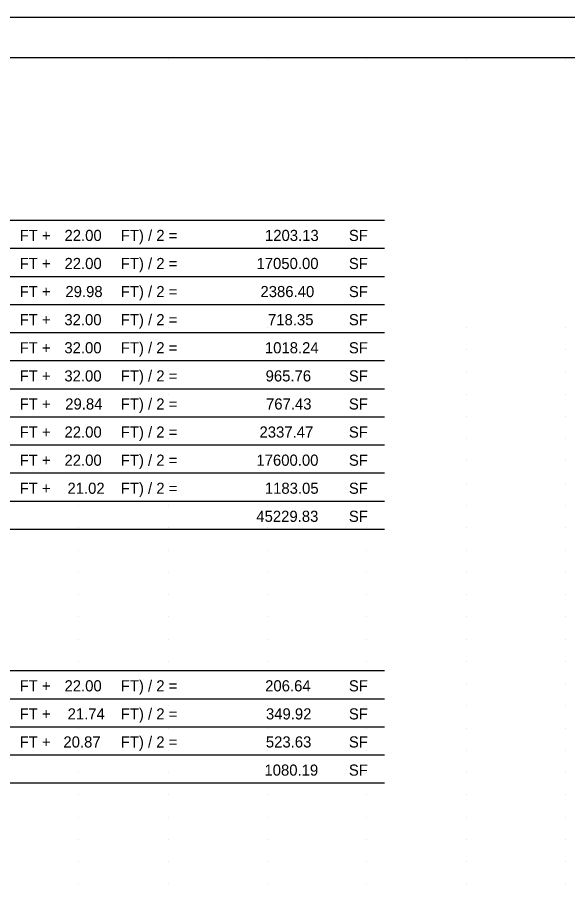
# Model space of a CAD drawing. Extents: x 2073163.5 to 2073197.5, y 634076.4 to 634098.4.
# Drawn here: x 2073173.43 to 2073180.34, y 634087.36 to 634098.43 of the extents above; entities that cross this region are included whole.
import ezdxf

# ---------------------------------------------------------------- set-up
doc = ezdxf.new("R2010")
doc.units = 0
for name, color, linetype in [('SC_Scratch1', 7, 'Continuous'), ('SH_Border', 7, 'Continuous'), ('SH_Cut_Line', 7, 'Continuous'), ('SH_Data', 7, 'Continuous'), ('SH_Text', 7, 'Continuous')]:
    doc.layers.add(name, color=color, linetype=linetype)

msp = doc.modelspace()

# ---------------------------------------------------------------- linework, layer by layer
at = {"layer": 'SC_Scratch1'}
for p, q in [((2073165.829, 634095.887), (2073178.043, 634095.887)), ((2073165.829, 634095.533), (2073178.043, 634095.533)), ((2073165.829, 634095.18), (2073178.043, 634095.18)), ((2073165.829, 634094.827), (2073178.043, 634094.827)), ((2073165.829, 634094.473), (2073178.043, 634094.473)), ((2073165.829, 634094.12), (2073178.043, 634094.12)), ((2073165.829, 634093.767), (2073178.043, 634093.767)), ((2073165.829, 634093.413), (2073178.043, 634093.413)), ((2073165.829, 634093.06), (2073178.043, 634093.06)), ((2073165.829, 634092.707), (2073178.043, 634092.707)), ((2073165.829, 634092.353), (2073178.043, 634092.353)), ((2073165.829, 634092), (2073178.043, 634092)), ((2073165.829, 634090.222), (2073178.043, 634090.222)), ((2073165.829, 634089.868), (2073178.043, 634089.868)), ((2073165.829, 634089.515), (2073178.043, 634089.515)), ((2073165.829, 634089.162), (2073178.043, 634089.162)), ((2073165.829, 634088.808), (2073178.043, 634088.808))]:
    msp.add_line(p, q, dxfattribs=at)
at = {"layer": 'SH_Border'}
msp.add_lwpolyline([(2073165.007, 634097.934), (2073197.007, 634097.934), (2073197.007, 634076.934), (2073165.007, 634076.934)], close=True, dxfattribs=at)
at = {"layer": 'SH_Cut_Line'}
msp.add_lwpolyline([(2073163.507, 634076.434), (2073197.507, 634076.434), (2073197.507, 634098.434), (2073163.507, 634098.434)], close=True, dxfattribs=at)
at = {"layer": 'SH_Data'}
for p, q in [((2073175.321, 634097.91), (2073175.321, 634097.91)), ((2073176.571, 634097.91), (2073176.571, 634097.91)), ((2073177.821, 634097.91), (2073177.821, 634097.91)), ((2073179.071, 634097.91), (2073179.071, 634097.91)), ((2073180.321, 634097.91), (2073180.321, 634097.91)), ((2073175.321, 634094.538), (2073175.321, 634094.538)), ((2073176.571, 634094.538), (2073176.571, 634094.538)), ((2073177.821, 634094.538), (2073177.821, 634094.538)), ((2073179.071, 634094.538), (2073179.071, 634094.538)), ((2073180.321, 634094.538), (2073180.321, 634094.538)), ((2073174.196, 634094.258), (2073174.196, 634094.258)), ((2073175.321, 634094.258), (2073175.321, 634094.258)), ((2073176.571, 634094.258), (2073176.571, 634094.258)), ((2073177.821, 634094.258), (2073177.821, 634094.258)), ((2073179.071, 634094.258), (2073179.071, 634094.258)), ((2073180.321, 634094.258), (2073180.321, 634094.258)), ((2073174.196, 634093.978), (2073174.196, 634093.978)), ((2073175.321, 634093.978), (2073175.321, 634093.978)), ((2073176.571, 634093.978), (2073176.571, 634093.978)), ((2073177.821, 634093.978), (2073177.821, 634093.978)), ((2073179.071, 634093.978), (2073179.071, 634093.978)), ((2073180.321, 634093.978), (2073180.321, 634093.978)), ((2073174.196, 634093.698), (2073174.196, 634093.698)), ((2073175.321, 634093.698), (2073175.321, 634093.698)), ((2073176.571, 634093.698), (2073176.571, 634093.698)), ((2073177.821, 634093.698), (2073177.821, 634093.698)), ((2073179.071, 634093.698), (2073179.071, 634093.698)), ((2073180.321, 634093.698), (2073180.321, 634093.698)), ((2073174.196, 634093.418), (2073174.196, 634093.418)), ((2073175.321, 634093.418), (2073175.321, 634093.418)), ((2073176.571, 634093.418), (2073176.571, 634093.418)), ((2073177.821, 634093.418), (2073177.821, 634093.418)), ((2073179.071, 634093.418), (2073179.071, 634093.418)), ((2073180.321, 634093.418), (2073180.321, 634093.418)), ((2073174.196, 634093.138), (2073174.196, 634093.138)), ((2073175.321, 634093.138), (2073175.321, 634093.138)), ((2073176.571, 634093.138), (2073176.571, 634093.138)), ((2073177.821, 634093.138), (2073177.821, 634093.138)), ((2073179.071, 634093.138), (2073179.071, 634093.138)), ((2073180.321, 634093.138), (2073180.321, 634093.138)), ((2073174.196, 634092.858), (2073174.196, 634092.858)), ((2073175.321, 634092.858), (2073175.321, 634092.858)), ((2073176.571, 634092.858), (2073176.571, 634092.858)), ((2073177.821, 634092.858), (2073177.821, 634092.858)), ((2073179.071, 634092.858), (2073179.071, 634092.858)), ((2073180.321, 634092.858), (2073180.321, 634092.858)), ((2073174.196, 634092.578), (2073174.196, 634092.578)), ((2073175.321, 634092.578), (2073175.321, 634092.578)), ((2073176.571, 634092.578), (2073176.571, 634092.578)), ((2073177.821, 634092.578), (2073177.821, 634092.578)), ((2073179.071, 634092.578), (2073179.071, 634092.578)), ((2073180.321, 634092.578), (2073180.321, 634092.578)), ((2073174.196, 634092.298), (2073174.196, 634092.298)), ((2073175.321, 634092.298), (2073175.321, 634092.298)), ((2073176.571, 634092.298), (2073176.571, 634092.298)), ((2073177.821, 634092.298), (2073177.821, 634092.298)), ((2073179.071, 634092.298), (2073179.071, 634092.298)), ((2073180.321, 634092.298), (2073180.321, 634092.298)), ((2073174.196, 634092.018), (2073174.196, 634092.018)), ((2073175.321, 634092.018), (2073175.321, 634092.018)), ((2073176.571, 634092.018), (2073176.571, 634092.018)), ((2073177.821, 634092.018), (2073177.821, 634092.018)), ((2073179.071, 634092.018), (2073179.071, 634092.018)), ((2073180.321, 634092.018), (2073180.321, 634092.018)), ((2073174.196, 634091.738), (2073174.196, 634091.738)), ((2073175.321, 634091.738), (2073175.321, 634091.738)), ((2073176.571, 634091.738), (2073176.571, 634091.738)), ((2073177.821, 634091.738), (2073177.821, 634091.738)), ((2073179.071, 634091.738), (2073179.071, 634091.738)), ((2073180.321, 634091.738), (2073180.321, 634091.738)), ((2073174.196, 634091.458), (2073174.196, 634091.458)), ((2073175.321, 634091.458), (2073175.321, 634091.458)), ((2073176.571, 634091.458), (2073176.571, 634091.458)), ((2073177.821, 634091.458), (2073177.821, 634091.458)), ((2073179.071, 634091.458), (2073179.071, 634091.458)), ((2073180.321, 634091.458), (2073180.321, 634091.458)), ((2073174.196, 634091.178), (2073174.196, 634091.178)), ((2073175.321, 634091.178), (2073175.321, 634091.178)), ((2073176.571, 634091.178), (2073176.571, 634091.178)), ((2073177.821, 634091.178), (2073177.821, 634091.178)), ((2073179.071, 634091.178), (2073179.071, 634091.178)), ((2073180.321, 634091.178), (2073180.321, 634091.178)), ((2073174.196, 634090.898), (2073174.196, 634090.898)), ((2073175.321, 634090.898), (2073175.321, 634090.898)), ((2073176.571, 634090.898), (2073176.571, 634090.898)), ((2073177.821, 634090.898), (2073177.821, 634090.898)), ((2073179.071, 634090.898), (2073179.071, 634090.898)), ((2073180.321, 634090.898), (2073180.321, 634090.898)), ((2073174.196, 634090.618), (2073174.196, 634090.618)), ((2073175.321, 634090.618), (2073175.321, 634090.618)), ((2073176.571, 634090.618), (2073176.571, 634090.618)), ((2073177.821, 634090.618), (2073177.821, 634090.618)), ((2073179.071, 634090.618), (2073179.071, 634090.618)), ((2073180.321, 634090.618), (2073180.321, 634090.618)), ((2073174.196, 634090.338), (2073174.196, 634090.338)), ((2073175.321, 634090.338), (2073175.321, 634090.338)), ((2073176.571, 634090.338), (2073176.571, 634090.338)), ((2073177.821, 634090.338), (2073177.821, 634090.338)), ((2073179.071, 634090.338), (2073179.071, 634090.338)), ((2073180.321, 634090.338), (2073180.321, 634090.338)), ((2073174.196, 634090.058), (2073174.196, 634090.058)), ((2073175.321, 634090.058), (2073175.321, 634090.058)), ((2073176.571, 634090.058), (2073176.571, 634090.058)), ((2073177.821, 634090.058), (2073177.821, 634090.058)), ((2073179.071, 634090.058), (2073179.071, 634090.058)), ((2073180.321, 634090.058), (2073180.321, 634090.058)), ((2073174.196, 634089.778), (2073174.196, 634089.778)), ((2073175.321, 634089.778), (2073175.321, 634089.778)), ((2073176.571, 634089.778), (2073176.571, 634089.778)), ((2073177.821, 634089.778), (2073177.821, 634089.778)), ((2073179.071, 634089.778), (2073179.071, 634089.778)), ((2073180.321, 634089.778), (2073180.321, 634089.778)), ((2073174.196, 634089.498), (2073174.196, 634089.498)), ((2073175.321, 634089.498), (2073175.321, 634089.498)), ((2073176.571, 634089.498), (2073176.571, 634089.498)), ((2073177.821, 634089.498), (2073177.821, 634089.498)), ((2073179.071, 634089.498), (2073179.071, 634089.498)), ((2073180.321, 634089.498), (2073180.321, 634089.498)), ((2073174.196, 634089.218), (2073174.196, 634089.218)), ((2073175.321, 634089.218), (2073175.321, 634089.218)), ((2073176.571, 634089.218), (2073176.571, 634089.218)), ((2073177.821, 634089.218), (2073177.821, 634089.218)), ((2073179.071, 634089.218), (2073179.071, 634089.218)), ((2073180.321, 634089.218), (2073180.321, 634089.218)), ((2073174.196, 634088.938), (2073174.196, 634088.938)), ((2073175.321, 634088.938), (2073175.321, 634088.938)), ((2073176.571, 634088.938), (2073176.571, 634088.938)), ((2073177.821, 634088.938), (2073177.821, 634088.938)), ((2073179.071, 634088.938), (2073179.071, 634088.938)), ((2073180.321, 634088.938), (2073180.321, 634088.938)), ((2073174.196, 634088.658), (2073174.196, 634088.658)), ((2073175.321, 634088.658), (2073175.321, 634088.658)), ((2073176.571, 634088.658), (2073176.571, 634088.658)), ((2073177.821, 634088.658), (2073177.821, 634088.658)), ((2073179.071, 634088.658), (2073179.071, 634088.658)), ((2073180.321, 634088.658), (2073180.321, 634088.658)), ((2073174.196, 634088.378), (2073174.196, 634088.378)), ((2073175.321, 634088.378), (2073175.321, 634088.378)), ((2073176.571, 634088.378), (2073176.571, 634088.378)), ((2073177.821, 634088.378), (2073177.821, 634088.378)), ((2073179.071, 634088.378), (2073179.071, 634088.378)), ((2073180.321, 634088.378), (2073180.321, 634088.378)), ((2073174.196, 634088.098), (2073174.196, 634088.098)), ((2073175.321, 634088.098), (2073175.321, 634088.098)), ((2073176.571, 634088.098), (2073176.571, 634088.098)), ((2073177.821, 634088.098), (2073177.821, 634088.098)), ((2073179.071, 634088.098), (2073179.071, 634088.098)), ((2073180.321, 634088.098), (2073180.321, 634088.098)), ((2073174.196, 634087.818), (2073174.196, 634087.818)), ((2073175.321, 634087.818), (2073175.321, 634087.818)), ((2073176.571, 634087.818), (2073176.571, 634087.818)), ((2073177.821, 634087.818), (2073177.821, 634087.818)), ((2073179.071, 634087.818), (2073179.071, 634087.818)), ((2073180.321, 634087.818), (2073180.321, 634087.818)), ((2073174.196, 634087.538), (2073174.196, 634087.538)), ((2073175.321, 634087.538), (2073175.321, 634087.538)), ((2073176.571, 634087.538), (2073176.571, 634087.538)), ((2073177.821, 634087.538), (2073177.821, 634087.538)), ((2073179.071, 634087.538), (2073179.071, 634087.538)), ((2073180.321, 634087.538), (2073180.321, 634087.538))]:
    msp.add_line(p, q, dxfattribs=at)

# ---------------------------------------------------------------- texts
at = {"layer": 'SH_Text'}
for s, p in [('FT +', (2073173.451, 634095.625)), ('22.00', (2073174.016, 634095.625)), ('FT) / 2 =', (2073174.724, 634095.625)), ('1203.13', (2073176.539, 634095.625)), ('SF ', (2073177.595, 634095.625)), ('FT) / 2 =', (2073174.724, 634095.272)), ('FT +', (2073173.451, 634095.272)), ('22.00', (2073174.016, 634095.272)), ('17050.00', (2073176.432, 634095.272)), ('SF ', (2073177.595, 634095.272)), ('FT +', (2073173.451, 634094.919)), ('29.98', (2073174.027, 634094.919)), ('FT) / 2 =', (2073174.724, 634094.919)), ('2386.40', (2073176.482, 634094.919)), ('SF ', (2073177.595, 634094.919)), ('FT +', (2073173.451, 634094.565)), ('32.00', (2073174.014, 634094.565)), ('FT) / 2 =', (2073174.724, 634094.565)), ('718.35', (2073176.577, 634094.565)), ('SF ', (2073177.595, 634094.565)), ('FT +', (2073173.451, 634094.212)), ('32.00', (2073174.014, 634094.212)), ('FT) / 2 =', (2073174.724, 634094.212)), ('1018.24', (2073176.538, 634094.212)), ('SF ', (2073177.595, 634094.212)), ('FT +', (2073173.451, 634093.858)), ('32.00', (2073174.014, 634093.858)), ('FT) / 2 =', (2073174.724, 634093.858)), ('965.76', (2073176.547, 634093.858)), ('SF ', (2073177.595, 634093.858)), ('FT +', (2073173.451, 634093.505)), ('29.84', (2073174.025, 634093.505)), ('FT) / 2 =', (2073174.724, 634093.505)), ('767.43', (2073176.552, 634093.505)), ('SF ', (2073177.595, 634093.505)), ('FT +', (2073173.451, 634093.152)), ('22.00', (2073174.016, 634093.152)), ('FT) / 2 =', (2073174.724, 634093.152)), ('2337.47', (2073176.47, 634093.152)), ('SF ', (2073177.595, 634093.152)), ('FT +', (2073173.451, 634092.798)), ('22.00', (2073174.016, 634092.798)), ('FT) / 2 =', (2073174.724, 634092.798)), ('17600.00', (2073176.431, 634092.798)), ('SF ', (2073177.595, 634092.798)), ('FT +', (2073173.451, 634092.445)), ('21.02', (2073174.053, 634092.445)), ('FT) / 2 =', (2073174.724, 634092.445)), ('1183.05', (2073176.537, 634092.445)), ('SF ', (2073177.595, 634092.445)), ('45229.83', (2073176.43, 634092.092)), ('SF ', (2073177.595, 634092.092)), ('FT +', (2073173.451, 634089.96)), ('22.00', (2073174.016, 634089.96)), ('FT) / 2 =', (2073174.724, 634089.96)), ('206.64', (2073176.541, 634089.96)), ('SF ', (2073177.595, 634089.96)), ('FT +', (2073173.451, 634089.607)), ('21.74', (2073174.055, 634089.607)), ('FT) / 2 =', (2073174.724, 634089.607)), ('349.92', (2073176.551, 634089.607)), ('SF ', (2073177.595, 634089.607)), ('FT +', (2073173.451, 634089.254)), ('20.87', (2073174.002, 634089.254)), ('FT) / 2 =', (2073174.724, 634089.254)), ('523.63', (2073176.55, 634089.254)), ('SF ', (2073177.595, 634089.254)), ('1080.19', (2073176.532, 634088.9)), ('SF ', (2073177.595, 634088.9))]:
    msp.add_text(s, height=0.14, rotation=0.0001, dxfattribs=at).set_placement(p)

doc.saveas('drawing.dxf')
